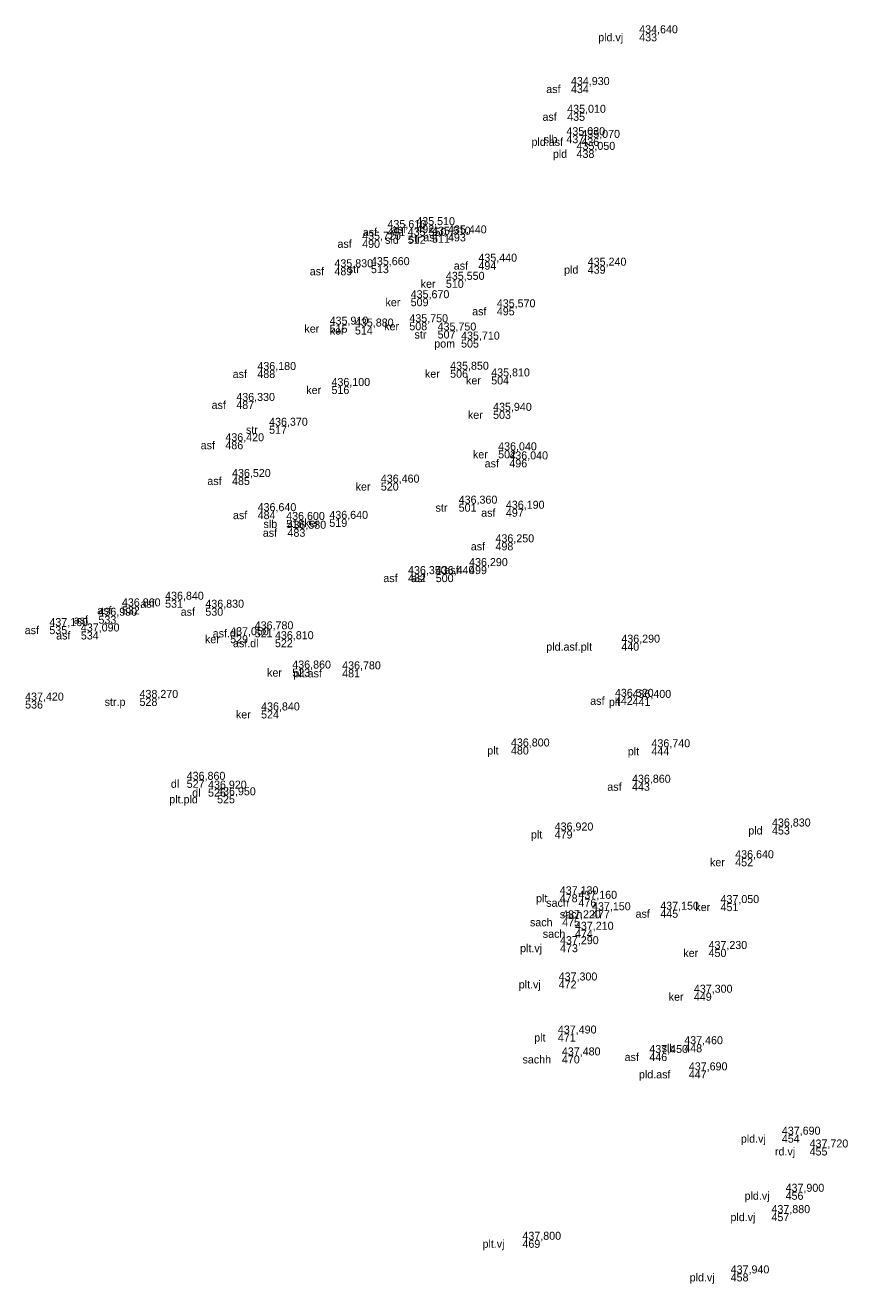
# Model space of a CAD drawing. Extents: x -747136 to -746138, y -1093274 to -1091717.
# Drawn here: x -746667.05 to -746636.2, y -1093078.89 to -1093031.72 of the extents above; entities that cross this region are included whole.
import ezdxf

# ---------------------------------------------------------------- set-up
doc = ezdxf.new("R2010")
doc.units = 0
for name, color, linetype in [('1029', 7, 'Continuous'), ('404', 7, 'Continuous'), ('424', 7, 'Continuous')]:
    doc.layers.add(name, color=color, linetype=linetype)

msp = doc.modelspace()

# ---------------------------------------------------------------- linework, layer by layer
at = {"layer": '404'}
for p, q in [((-746644.02, -1093032.02), (-746644.02, -1093032.02)), ((-746646.58, -1093033.96), (-746646.58, -1093033.96)), ((-746646.72, -1093035), (-746646.72, -1093035)), ((-746646.75, -1093035.84), (-746646.75, -1093035.84)), ((-746646.19, -1093035.94), (-746646.19, -1093035.94)), ((-746646.37, -1093036.39), (-746646.37, -1093036.39)), ((-746653.46, -1093039.32), (-746653.46, -1093039.32)), ((-746652.38, -1093039.21), (-746652.38, -1093039.21)), ((-746651.79, -1093039.57), (-746651.79, -1093039.57)), ((-746651.19, -1093039.52), (-746651.19, -1093039.52)), ((-746654.41, -1093039.76), (-746654.41, -1093039.76)), ((-746652.7, -1093039.61), (-746652.7, -1093039.61)), ((-746655.45, -1093040.79), (-746655.45, -1093040.79)), ((-746654.08, -1093040.71), (-746654.08, -1093040.71)), ((-746650.05, -1093040.58), (-746650.05, -1093040.58)), ((-746645.95, -1093040.73), (-746645.95, -1093040.73)), ((-746651.27, -1093041.26), (-746651.27, -1093041.26)), ((-746652.59, -1093041.95), (-746652.59, -1093041.95)), ((-746649.36, -1093042.29), (-746649.36, -1093042.29)), ((-746652.64, -1093042.85), (-746652.64, -1093042.85)), ((-746655.63, -1093042.94), (-746655.63, -1093042.94)), ((-746654.68, -1093043.01), (-746654.68, -1093043.01)), ((-746651.58, -1093043.16), (-746651.58, -1093043.16)), ((-746650.7, -1093043.5), (-746650.7, -1093043.5)), ((-746658.34, -1093044.64), (-746658.34, -1093044.64)), ((-746651.11, -1093044.63), (-746651.11, -1093044.63)), ((-746655.56, -1093045.24), (-746655.56, -1093045.24)), ((-746649.57, -1093044.88), (-746649.57, -1093044.88)), ((-746659.13, -1093045.8), (-746659.13, -1093045.8)), ((-746649.5, -1093046.17), (-746649.5, -1093046.17)), ((-746657.9, -1093046.73), (-746657.9, -1093046.73)), ((-746659.54, -1093047.31), (-746659.54, -1093047.31)), ((-746649.31, -1093047.65), (-746649.31, -1093047.65)), ((-746648.89, -1093047.99), (-746648.89, -1093047.99)), ((-746659.29, -1093048.65), (-746659.29, -1093048.65)), ((-746653.71, -1093048.86), (-746653.71, -1093048.86)), ((-746658.33, -1093049.93), (-746658.33, -1093049.93)), ((-746650.79, -1093049.65), (-746650.79, -1093049.65)), ((-746649.02, -1093049.84), (-746649.02, -1093049.84)), ((-746657.26, -1093050.26), (-746657.26, -1093050.26)), ((-746655.64, -1093050.22), (-746655.64, -1093050.22)), ((-746657.21, -1093050.59), (-746657.21, -1093050.59)), ((-746649.41, -1093051.1), (-746649.41, -1093051.1)), ((-746652.69, -1093052.29), (-746652.69, -1093052.29)), ((-746651.65, -1093052.29), (-746651.65, -1093052.29)), ((-746650.4, -1093051.99), (-746650.4, -1093051.99)), ((-746661.8, -1093053.25), (-746661.8, -1093053.25)), ((-746663.42, -1093053.5), (-746663.42, -1093053.5)), ((-746660.29, -1093053.55), (-746660.29, -1093053.55)), ((-746664.3, -1093053.85), (-746664.3, -1093053.85)), ((-746666.14, -1093054.24), (-746666.14, -1093054.24)), ((-746664.96, -1093054.44), (-746664.96, -1093054.44)), ((-746659.36, -1093054.58), (-746659.36, -1093054.58)), ((-746658.44, -1093054.36), (-746658.44, -1093054.36)), ((-746657.68, -1093054.73), (-746657.68, -1093054.73)), ((-746644.69, -1093054.86), (-746644.69, -1093054.86)), ((-746657.03, -1093055.83), (-746657.03, -1093055.83)), ((-746655.16, -1093055.86), (-746655.16, -1093055.86)), ((-746662.76, -1093056.93), (-746662.76, -1093056.93)), ((-746644.93, -1093056.89), (-746644.93, -1093056.89)), ((-746644.27, -1093056.93), (-746644.27, -1093056.93)), ((-746658.2, -1093057.4), (-746658.2, -1093057.4)), ((-746648.83, -1093058.75), (-746648.83, -1093058.75)), ((-746643.56, -1093058.78), (-746643.56, -1093058.78)), ((-746660.99, -1093060), (-746660.99, -1093060)), ((-746660.19, -1093060.33), (-746660.19, -1093060.33)), ((-746644.29, -1093060.11), (-746644.29, -1093060.11)), ((-746659.85, -1093060.58), (-746659.85, -1093060.58)), ((-746639.04, -1093061.75), (-746639.04, -1093061.75)), ((-746647.19, -1093061.9), (-746647.19, -1093061.9)), ((-746640.42, -1093062.94), (-746640.42, -1093062.94)), ((-746647, -1093064.29), (-746647, -1093064.29)), ((-746646.3, -1093064.46), (-746646.3, -1093064.46)), ((-746645.79, -1093064.89), (-746645.79, -1093064.89)), ((-746643.23, -1093064.87), (-746643.23, -1093064.87)), ((-746640.97, -1093064.62), (-746640.97, -1093064.62)), ((-746646.91, -1093065.19), (-746646.91, -1093065.19)), ((-746646.43, -1093065.62), (-746646.43, -1093065.62)), ((-746646.99, -1093066.16), (-746646.99, -1093066.16)), ((-746641.42, -1093066.34), (-746641.42, -1093066.34)), ((-746647.04, -1093067.52), (-746647.04, -1093067.52)), ((-746641.97, -1093067.98), (-746641.97, -1093067.98)), ((-746647.07, -1093069.51), (-746647.07, -1093069.51)), ((-746643.64, -1093070.24), (-746643.64, -1093070.24)), ((-746642.33, -1093069.91), (-746642.33, -1093069.91)), ((-746646.92, -1093070.33), (-746646.92, -1093070.33)), ((-746642.16, -1093070.89), (-746642.16, -1093070.89)), ((-746638.67, -1093073.3), (-746638.67, -1093073.3)), ((-746637.63, -1093073.78), (-746637.63, -1093073.78)), ((-746638.53, -1093075.44), (-746638.53, -1093075.44)), ((-746639.06, -1093076.24), (-746639.06, -1093076.24)), ((-746648.4, -1093077.24), (-746648.4, -1093077.24)), ((-746640.59, -1093078.5), (-746640.59, -1093078.5))]:
    msp.add_line(p, q, dxfattribs=at)

# ---------------------------------------------------------------- texts
at = {"layer": '1029'}
for s, p in [('434,640', (-746644.02, -1093032.02)), ('434,930', (-746646.58, -1093033.96)), ('435,010', (-746646.72, -1093035)), ('435,030', (-746646.75, -1093035.84)), ('435,070', (-746646.19, -1093035.94)), ('435,050', (-746646.37, -1093036.39)), ('435,610', (-746653.46, -1093039.32)), ('435,510', (-746652.38, -1093039.21)), ('435,720', (-746654.41, -1093039.76)), ('435,550', (-746652.7, -1093039.61)), ('435,510', (-746651.79, -1093039.57)), ('435,440', (-746651.19, -1093039.52)), ('435,830', (-746655.45, -1093040.79)), ('435,660', (-746654.08, -1093040.71)), ('435,440', (-746650.05, -1093040.58)), ('435,240', (-746645.95, -1093040.73)), ('435,550', (-746651.27, -1093041.26)), ('435,670', (-746652.59, -1093041.95)), ('435,570', (-746649.36, -1093042.29)), ('435,910', (-746655.63, -1093042.94)), ('435,880', (-746654.68, -1093043.01)), ('435,750', (-746652.64, -1093042.85)), ('435,750', (-746651.58, -1093043.16)), ('435,710', (-746650.7, -1093043.5)), ('436,180', (-746658.34, -1093044.64)), ('435,850', (-746651.11, -1093044.63)), ('435,810', (-746649.57, -1093044.88)), ('436,100', (-746655.56, -1093045.24)), ('436,330', (-746659.13, -1093045.8)), ('435,940', (-746649.5, -1093046.17)), ('436,370', (-746657.9, -1093046.73)), ('436,420', (-746659.54, -1093047.31)), ('436,040', (-746649.31, -1093047.65)), ('436,040', (-746648.89, -1093047.99)), ('436,520', (-746659.29, -1093048.65)), ('436,460', (-746653.71, -1093048.86)), ('436,360', (-746650.79, -1093049.65)), ('436,640', (-746658.33, -1093049.93)), ('436,600', (-746657.26, -1093050.26)), ('436,640', (-746655.64, -1093050.22)), ('436,190', (-746649.02, -1093049.84)), ('436,580', (-746657.21, -1093050.59)), ('436,250', (-746649.41, -1093051.1)), ('436,290', (-746650.4, -1093051.99)), ('436,350', (-746652.69, -1093052.29)), ('436,440', (-746651.65, -1093052.29)), ('436,860', (-746663.42, -1093053.5)), ('436,840', (-746661.8, -1093053.25)), ('436,830', (-746660.29, -1093053.55)), ('436,990', (-746664.3, -1093053.85)), ('437,160', (-746666.14, -1093054.24)), ('437,090', (-746664.96, -1093054.44)), ('436,780', (-746658.44, -1093054.36)), ('437,050', (-746659.36, -1093054.58)), ('436,810', (-746657.68, -1093054.73)), ('436,290', (-746644.69, -1093054.86)), ('436,860', (-746657.03, -1093055.83)), ('436,780', (-746655.16, -1093055.86)), ('437,420', (-746667.05, -1093057.03)), ('438,270', (-746662.76, -1093056.93)), ('436,520', (-746644.93, -1093056.89)), ('436,400', (-746644.27, -1093056.93)), ('436,840', (-746658.2, -1093057.4)), ('436,800', (-746648.83, -1093058.75)), ('436,740', (-746643.56, -1093058.78)), ('436,860', (-746660.99, -1093060)), ('436,860', (-746644.29, -1093060.11)), ('436,920', (-746660.19, -1093060.33)), ('436,950', (-746659.85, -1093060.58)), ('436,920', (-746647.19, -1093061.9)), ('436,830', (-746639.04, -1093061.75)), ('436,640', (-746640.42, -1093062.94)), ('437,130', (-746647, -1093064.29)), ('437,160', (-746646.3, -1093064.46)), ('437,150', (-746645.79, -1093064.89)), ('437,150', (-746643.23, -1093064.87)), ('437,050', (-746640.97, -1093064.62)), ('437,220', (-746646.91, -1093065.19)), ('437,210', (-746646.43, -1093065.62)), ('437,290', (-746646.99, -1093066.16)), ('437,230', (-746641.42, -1093066.34)), ('437,300', (-746647.04, -1093067.52)), ('437,300', (-746641.97, -1093067.98)), ('437,490', (-746647.07, -1093069.51)), ('437,460', (-746642.33, -1093069.91)), ('437,480', (-746646.92, -1093070.33)), ('437,450', (-746643.64, -1093070.24)), ('437,690', (-746642.16, -1093070.89)), ('437,690', (-746638.67, -1093073.3)), ('437,720', (-746637.63, -1093073.78)), ('437,900', (-746638.53, -1093075.44)), ('437,880', (-746639.06, -1093076.24)), ('437,800', (-746648.4, -1093077.24)), ('437,940', (-746640.59, -1093078.5))]:
    msp.add_text(s, height=0.3, dxfattribs=at).set_placement(p)
at = {"layer": '424'}
for s, p in [(' pld.vj', (-746645.669, -1093032.32)), ('433', (-746644.02, -1093032.32)), (' asf', (-746647.617, -1093034.26)), ('434', (-746646.58, -1093034.26)), (' asf', (-746647.757, -1093035.3)), ('435', (-746646.72, -1093035.3)), (' slb', (-746647.711, -1093036.14)), (' pld.asf', (-746648.171, -1093036.24)), ('437', (-746646.75, -1093036.14)), ('436', (-746646.19, -1093036.24)), (' pld', (-746647.369, -1093036.69)), ('438', (-746646.37, -1093036.69)), (' asf', (-746654.497, -1093039.62)), (' sld', (-746653.661, -1093039.91)), ('491', (-746653.46, -1093039.62)), (' asf', (-746653.417, -1093039.51)), (' str', (-746652.768, -1093039.87)), ('492', (-746652.38, -1093039.51)), (' asf', (-746652.227, -1093039.82)), ('511', (-746651.79, -1093039.87)), ('493', (-746651.19, -1093039.82)), (' asf', (-746655.447, -1093040.06)), ('490', (-746654.41, -1093040.06)), ('512', (-746652.7, -1093039.91)), (' asf', (-746656.487, -1093041.09)), ('489', (-746655.45, -1093041.09)), (' str', (-746655.058, -1093041.01)), ('513', (-746654.08, -1093041.01)), (' asf', (-746651.087, -1093040.88)), ('494', (-746650.05, -1093040.88)), (' pld', (-746646.949, -1093041.03)), ('439', (-746645.95, -1093041.03)), (' ker', (-746652.326, -1093041.56)), ('510', (-746651.27, -1093041.56)), (' ker', (-746653.646, -1093042.25)), ('509', (-746652.59, -1093042.25)), (' asf', (-746650.397, -1093042.59)), ('495', (-746649.36, -1093042.59)), (' ker', (-746653.696, -1093043.15)), ('508', (-746652.64, -1093043.15)), (' ker', (-746656.686, -1093043.24)), ('515', (-746655.63, -1093043.24)), (' ker', (-746655.736, -1093043.31)), ('514', (-746654.68, -1093043.31)), (' str', (-746652.558, -1093043.46)), ('507', (-746651.58, -1093043.46)), (' pom', (-746651.817, -1093043.8)), ('505', (-746650.7, -1093043.8)), (' asf', (-746659.377, -1093044.94)), ('488', (-746658.34, -1093044.94)), (' ker', (-746652.166, -1093044.93)), ('506', (-746651.11, -1093044.93)), (' ker', (-746656.616, -1093045.54)), ('516', (-746655.56, -1093045.54)), (' ker', (-746650.626, -1093045.18)), ('504', (-746649.57, -1093045.18)), (' asf', (-746660.167, -1093046.1)), ('487', (-746659.13, -1093046.1)), (' ker', (-746650.556, -1093046.47)), ('503', (-746649.5, -1093046.47)), (' str', (-746658.878, -1093047.03)), ('517', (-746657.9, -1093047.03)), (' asf', (-746660.577, -1093047.61)), ('486', (-746659.54, -1093047.61)), (' ker', (-746650.366, -1093047.95)), (' asf', (-746649.927, -1093048.29)), ('502', (-746649.31, -1093047.95)), ('496', (-746648.89, -1093048.29)), (' asf', (-746660.327, -1093048.95)), ('485', (-746659.29, -1093048.95)), (' ker', (-746654.766, -1093049.16)), ('520', (-746653.71, -1093049.16)), (' asf', (-746659.367, -1093050.23)), ('484', (-746658.33, -1093050.23)), (' str', (-746651.768, -1093049.95)), ('501', (-746650.79, -1093049.95)), (' asf', (-746650.057, -1093050.14)), ('497', (-746649.02, -1093050.14)), (' slb', (-746658.221, -1093050.56)), ('518', (-746657.26, -1093050.56)), (' ker', (-746656.696, -1093050.52)), ('519', (-746655.64, -1093050.52)), (' asf', (-746658.247, -1093050.89)), ('483', (-746657.21, -1093050.89)), (' asf', (-746650.447, -1093051.4)), ('498', (-746649.41, -1093051.4)), (' asf', (-746653.727, -1093052.59)), ('482', (-746652.69, -1093052.59)), (' asf', (-746652.687, -1093052.59)), ('500', (-746651.65, -1093052.59)), (' asf', (-746651.437, -1093052.29)), ('499', (-746650.4, -1093052.29)), (' asf', (-746662.837, -1093053.55)), ('531', (-746661.8, -1093053.55)), (' asf', (-746664.457, -1093053.8)), ('532', (-746663.42, -1093053.8)), (' asf', (-746661.327, -1093053.85)), ('530', (-746660.29, -1093053.85)), (' asf', (-746665.337, -1093054.15)), ('533', (-746664.3, -1093054.15)), (' asf', (-746667.177, -1093054.54)), ('535', (-746666.14, -1093054.54)), (' asf', (-746665.997, -1093054.74)), ('534', (-746664.96, -1093054.74)), (' ker', (-746660.416, -1093054.88)), (' asf.dl', (-746660.126, -1093054.66)), ('529', (-746659.36, -1093054.88)), ('521', (-746658.44, -1093054.66)), (' asf.dl', (-746659.366, -1093055.03)), ('522', (-746657.68, -1093055.03)), (' pld.asf.plt', (-746647.616, -1093055.16)), ('440', (-746644.69, -1093055.16)), (' ker', (-746658.086, -1093056.13)), ('523', (-746657.03, -1093056.13)), (' plt.asf', (-746657.101, -1093056.16)), ('481', (-746655.16, -1093056.16)), ('536', (-746667.05, -1093057.33)), (' str.p', (-746664.179, -1093057.23)), ('528', (-746662.76, -1093057.23)), (' asf', (-746645.967, -1093057.19)), (' plt', (-746645.269, -1093057.23)), ('442', (-746644.93, -1093057.19)), ('441', (-746644.27, -1093057.23)), (' ker', (-746659.256, -1093057.7)), ('524', (-746658.2, -1093057.7)), (' plt', (-746649.829, -1093059.05)), ('480', (-746648.83, -1093059.05)), (' plt', (-746644.559, -1093059.08)), ('444', (-746643.56, -1093059.08)), (' dl', (-746661.694, -1093060.3)), ('527', (-746660.99, -1093060.3)), (' dl', (-746660.894, -1093060.63)), ('526', (-746660.19, -1093060.63)), (' asf', (-746645.327, -1093060.41)), ('443', (-746644.29, -1093060.41)), (' plt.pld', (-746661.754, -1093060.88)), ('525', (-746659.85, -1093060.88)), (' pld', (-746640.039, -1093062.05)), ('453', (-746639.04, -1093062.05)), (' plt', (-746648.189, -1093062.2)), ('479', (-746647.19, -1093062.2)), (' ker', (-746641.476, -1093063.24)), ('452', (-746640.42, -1093063.24)), (' plt', (-746647.999, -1093064.59)), (' sach', (-746647.618, -1093064.76)), ('478', (-746647, -1093064.59)), ('476', (-746646.3, -1093064.76)), (' sach', (-746647.108, -1093065.19)), ('477', (-746645.79, -1093065.19)), (' asf', (-746644.267, -1093065.17)), ('445', (-746643.23, -1093065.17)), (' ker', (-746642.026, -1093064.92)), ('451', (-746640.97, -1093064.92)), (' sach', (-746648.228, -1093065.49)), ('475', (-746646.91, -1093065.49)), (' sach', (-746647.748, -1093065.92)), ('474', (-746646.43, -1093065.92)), (' plt.vj', (-746648.598, -1093066.46)), ('473', (-746646.99, -1093066.46)), (' ker', (-746642.476, -1093066.64)), ('450', (-746641.42, -1093066.64)), (' plt.vj', (-746648.648, -1093067.82)), ('472', (-746647.04, -1093067.82)), (' ker', (-746643.026, -1093068.28)), ('449', (-746641.97, -1093068.28)), (' plt', (-746648.069, -1093069.81)), ('471', (-746647.07, -1093069.81)), (' asf', (-746644.677, -1093070.54)), ('446', (-746643.64, -1093070.54)), (' slb', (-746643.291, -1093070.21)), ('448', (-746642.33, -1093070.21)), (' sachh', (-746648.507, -1093070.63)), ('470', (-746646.92, -1093070.63)), (' pld.asf', (-746644.141, -1093071.19)), ('447', (-746642.16, -1093071.19)), (' pld.vj', (-746640.319, -1093073.6)), ('454', (-746638.67, -1093073.6)), (' rd.vj', (-746639.04, -1093074.08)), ('455', (-746637.63, -1093074.08)), (' pld.vj', (-746640.179, -1093075.74)), ('456', (-746638.53, -1093075.74)), (' pld.vj', (-746640.709, -1093076.54)), ('457', (-746639.06, -1093076.54)), (' plt.vj', (-746650.008, -1093077.54)), ('469', (-746648.4, -1093077.54)), (' pld.vj', (-746642.239, -1093078.8)), ('458', (-746640.59, -1093078.8))]:
    msp.add_text(s, height=0.3, dxfattribs=at).set_placement(p)

doc.saveas('drawing.dxf')
